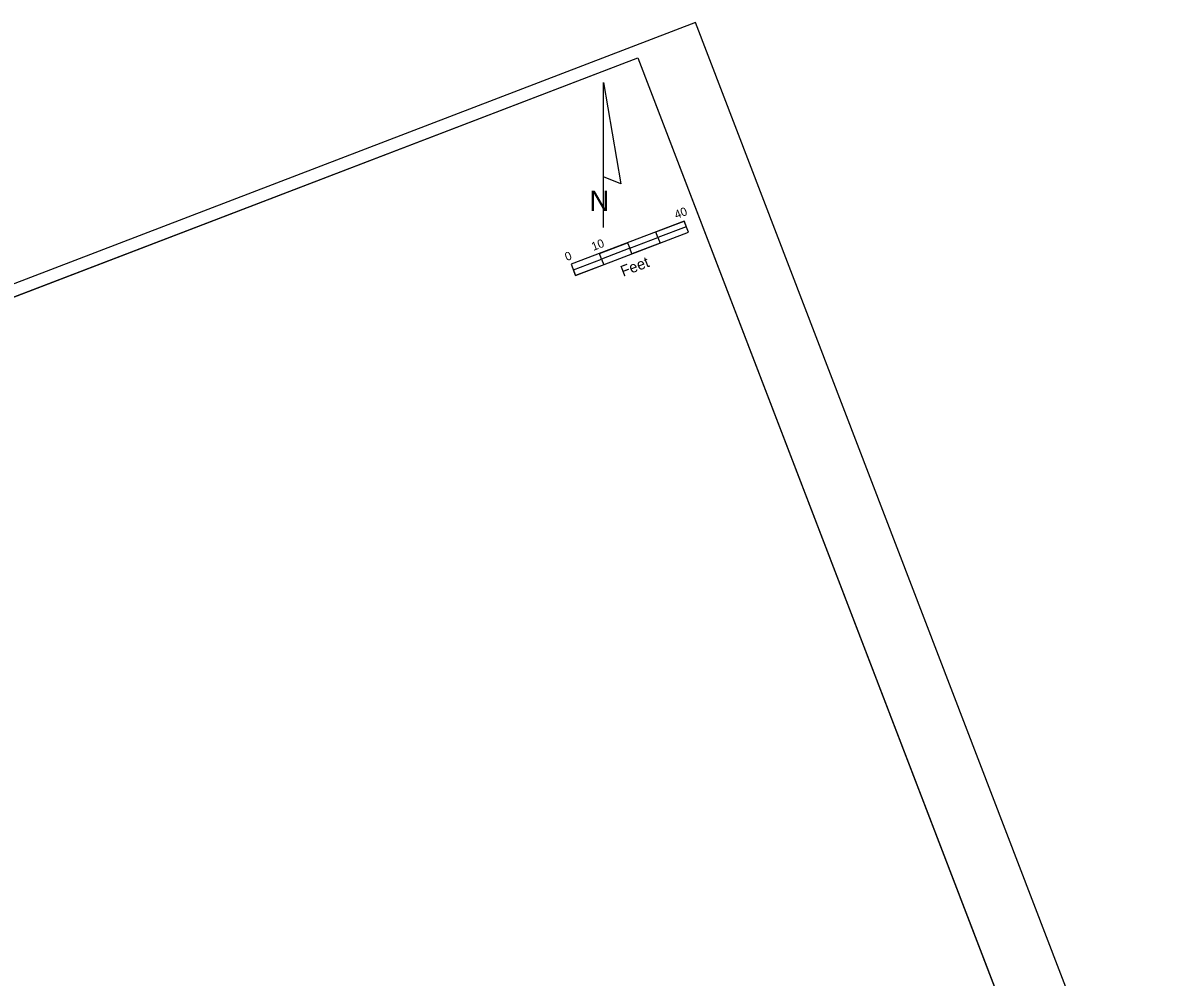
# Model space of a CAD drawing. Extents: x 510822 to 511590, y 1315307 to 1315940.
# Drawn here: x 511215.5 to 511590, y 1315623.6 to 1315939.7 of the extents above; entities that cross this region are included whole.
import ezdxf

# ---------------------------------------------------------------- set-up
doc = ezdxf.new("R2010")
doc.units = 0
for name, color, linetype in [('NonPlottingEle_dp', 7, 'Continuous'), ('NorthArw_dp', 7, 'Continuous'), ('PlotBorder_dp', 7, 'Continuous'), ('Scale_dp', 7, 'Continuous'), ('SheetBorder_dp', 7, 'Continuous')]:
    doc.layers.add(name, color=color, linetype=linetype)

msp = doc.modelspace()

# ---------------------------------------------------------------- linework, layer by layer
at = {"layer": 'NonPlottingEle_dp'}
msp.add_lwpolyline([(510843.86, 1315707.47), (511418.99, 1315928.11), (511556.54, 1315569.59), (510981.41, 1315348.95)], close=True, dxfattribs=at)
at = {"layer": 'NorthArw_dp'}
msp.add_line((511407.64, 1315871.91), (511407.64, 1315919.91), dxfattribs=at)
msp.add_lwpolyline([(511407.64, 1315888.71), (511407.64, 1315919.91), (511413.4, 1315886.31)], close=True, dxfattribs=at)
at = {"layer": 'PlotBorder_dp'}
msp.add_lwpolyline([(510973.76, 1315307.46), (511589.97, 1315543.86), (511438.1, 1315939.72), (510821.89, 1315703.32)], close=True, dxfattribs=at)
at = {"layer": 'Scale_dp'}
for p, q in [((511434.33, 1315874.02), (511396.98, 1315859.69)), ((511435.76, 1315870.29), (511434.33, 1315874.02)), ((511398.41, 1315855.96), (511435.76, 1315870.29)), ((511396.98, 1315859.69), (511398.41, 1315855.96))]:
    msp.add_line(p, q, dxfattribs=at)
for points in [[(511425.71, 1315868.57), (511424.99, 1315870.44), (511434.33, 1315874.02), (511435.04, 1315872.15)], [(511417.09, 1315863.12), (511416.37, 1315864.99), (511425.71, 1315868.57), (511426.42, 1315866.7)], [(511407.03, 1315861.41), (511406.32, 1315863.27), (511415.65, 1315866.86), (511416.37, 1315864.99)], [(511398.41, 1315855.96), (511397.7, 1315857.83), (511407.03, 1315861.41), (511407.75, 1315859.54)]]:
    msp.add_lwpolyline(points, close=True, dxfattribs=at)
at = {"layer": 'SheetBorder_dp'}
for p, q in [((510843.86, 1315707.47), (511418.99, 1315928.11)), ((511418.99, 1315928.11), (511568, 1315539.71))]:
    msp.add_line(p, q, dxfattribs=at)

# ---------------------------------------------------------------- texts
at = {"layer": 'NorthArw_dp'}
msp.add_text('N', height=6.72, dxfattribs=at).set_placement((511403.08, 1315877.34))
at = {"layer": 'Scale_dp'}
for s, height, p in [('40', 2.8, (511431.8, 1315874.66)), ('10', 2.8, (511404.33, 1315864.12)), ('0', 2.8, (511395.52, 1315860.74)), ('Feet', 3.6, (511414.17, 1315855.58))]:
    msp.add_text(s, height=height, rotation=20.9887, dxfattribs=at).set_placement(p)

doc.saveas('drawing.dxf')
